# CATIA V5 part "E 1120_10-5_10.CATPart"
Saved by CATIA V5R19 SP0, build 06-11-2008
Part number: E 1120_10-5_10
Definition: E 1120_10-5_10
Nomenclature: E 1120_10-5_10
Source: Unknown
Description: PART--DESC
Bounding box of the stored display mesh (mm): x 17 to 33, y -8 to 8, z -45 to -30
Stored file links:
  C:\Users\jsmid\Desktop\DP_Smidak_Forma LEGO\E 1120_10-5_10.CATPart
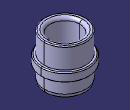
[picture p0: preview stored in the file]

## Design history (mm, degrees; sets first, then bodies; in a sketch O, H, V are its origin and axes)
Body1 "E 1120_10-5_10" (main body)
  Solid1: solid without history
